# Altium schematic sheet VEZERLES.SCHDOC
size A2
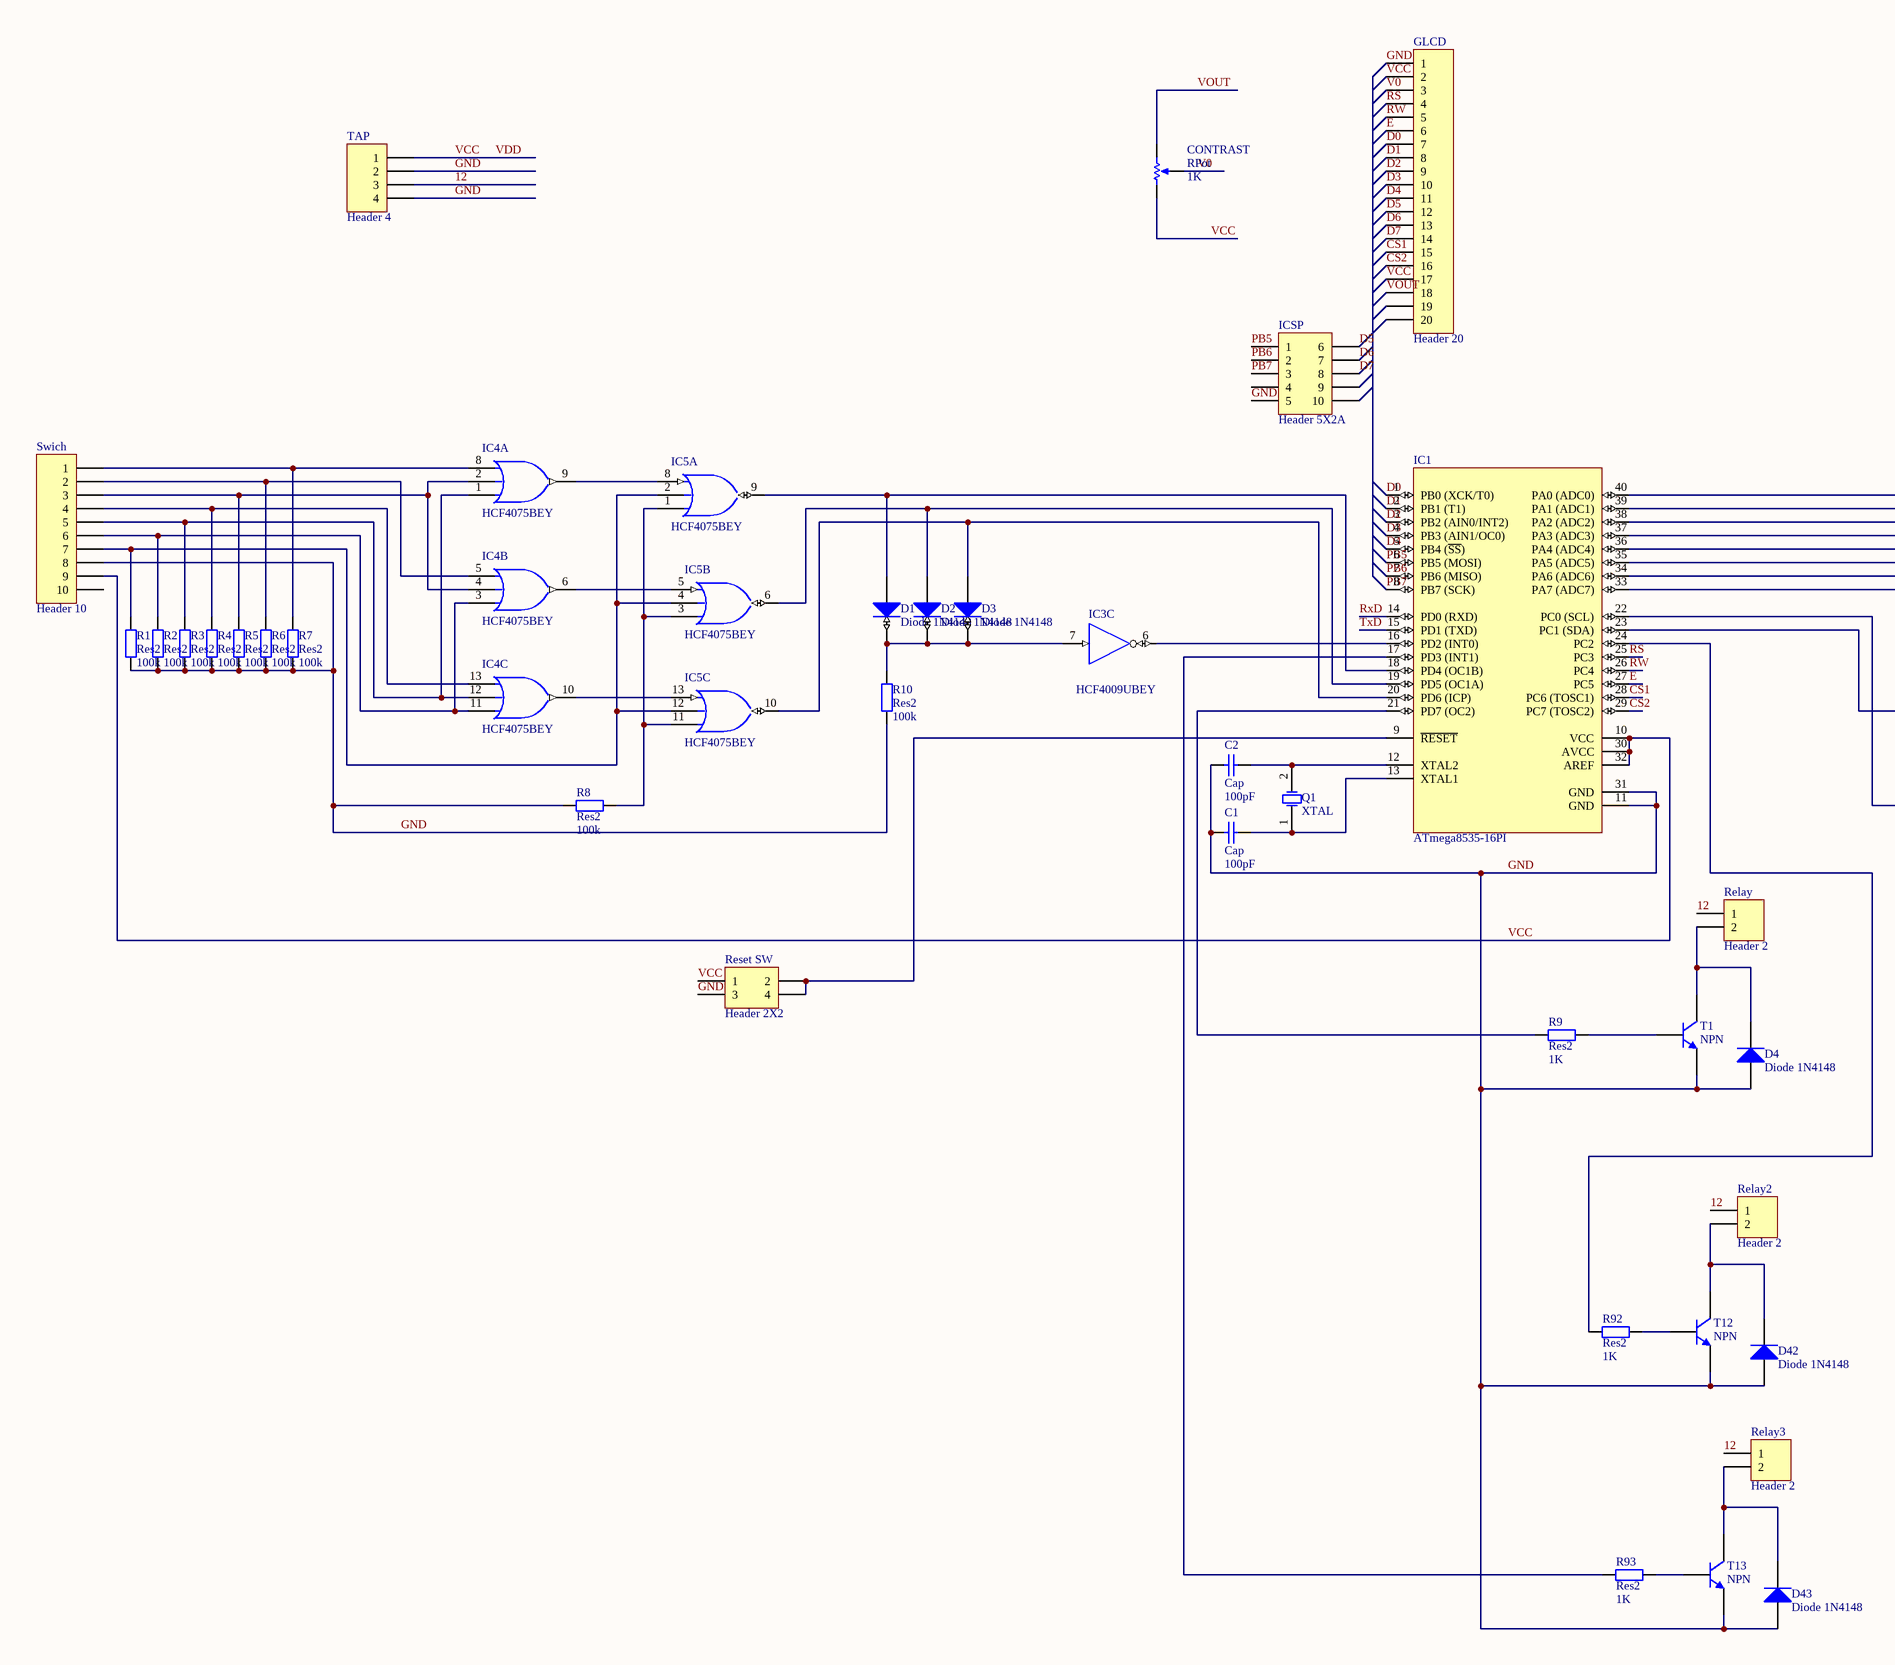
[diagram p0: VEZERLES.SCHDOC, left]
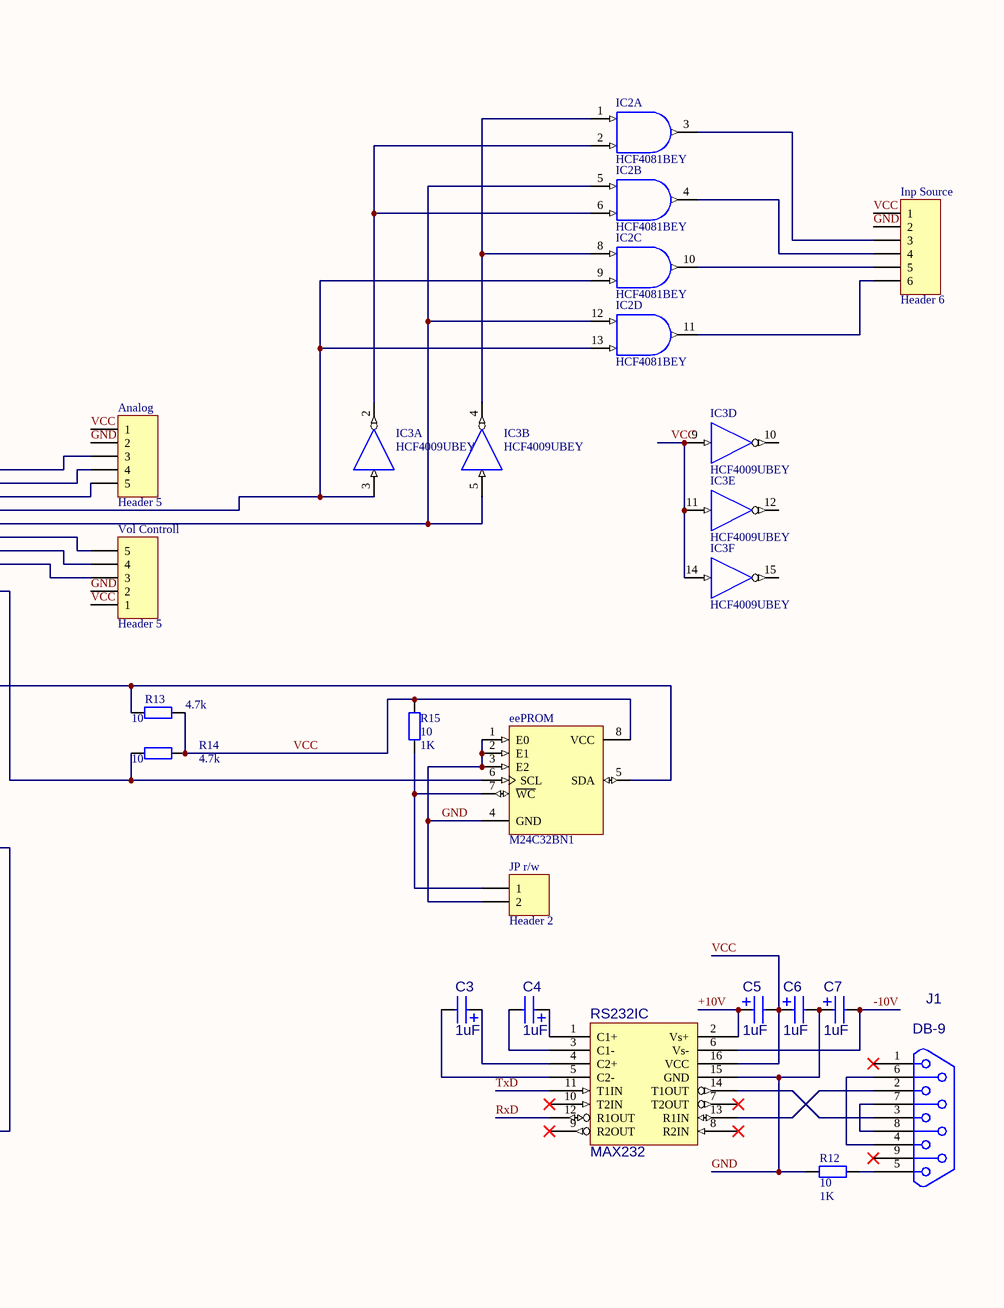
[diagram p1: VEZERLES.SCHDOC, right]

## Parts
Analog  Header 5  [HDR1X5]
C1  Cap  value 100pF  [CAPR2.54-5.1X3.2]
C2  Cap  value 100pF  [CAPR2.54-5.1X3.2]
C3  1uF  [CAPPR1.5-4X5]
C4  1uF  [CAPPR1.5-4X5]
C5  1uF  [CAPPR1.5-4X5]
C6  1uF  [CAPPR1.5-4X5]
C7  1uF  [CAPPR1.5-4X5]
CONTRAST  RPot  value 1K  [VR5]
D1  Diode 1N4148  [DIO7.1-3.9x1.9]
D2  Diode 1N4148  [DIO7.1-3.9x1.9]
D3  Diode 1N4148  [DIO7.1-3.9x1.9]
D4  Diode 1N4148  [DIO7.1-3.9x1.9]
D42  Diode 1N4148  [DIO7.1-3.9x1.9]
D43  Diode 1N4148  [DIO7.1-3.9x1.9]
eePROM  M24C32BN1  [PSDIP8A]
GLCD  Header 20  [HDR1X20]
IC1  ATmega8535-16PI  [40P6]
IC2  HCF4081BEY  [DIP14]  (parts A,B,C,D of 4)
IC3  HCF4009UBEY  [DIP16]  (parts A,B,C,D,E,F of 6)
IC4  HCF4075BEY  [DIP14]  (parts A,B,C of 3)
IC5  HCF4075BEY  [DIP14]  (parts A,B,C of 3)
ICSP  Header 5X2A  [HDR2X5_CEN]
Inp_Source  Header 6  [HDR1X6]
J1  DB-9  [DSUB1.385-2H9]
JP_r/w  Header 2  [HDR1X2]
Q1  XTAL  [BCY-W2/D3.1]
R1  Res2  value 100k  [AXIAL-0.4]
R2  Res2  value 100k  [AXIAL-0.4]
R3  Res2  value 100k  [AXIAL-0.4]
R4  Res2  value 100k  [AXIAL-0.4]
R5  Res2  value 100k  [AXIAL-0.4]
R6  Res2  value 100k  [AXIAL-0.4]
R7  Res2  value 100k  [AXIAL-0.4]
R8  Res2  value 100k  [AXIAL-0.4]
R9  Res2  value 1K  [AXIAL-0.4]
R10  Res2  value 100k  [AXIAL-0.4]
R12  10  value 1K  [AXIAL-0.4]
R13  10  value 4.7k  [AXIAL-0.4]
R14  10  value 4.7k  [AXIAL-0.4]
R15  10  value 1K  [AXIAL-0.4]
R92  Res2  value 1K  [AXIAL-0.4]
R93  Res2  value 1K  [AXIAL-0.4]
Relay  Header 2  [HDR1X2]
Relay2  Header 2  [HDR1X2]
Relay3  Header 2  [HDR1X2]
Reset_SW  Header 2X2  [HDR2X2]
RS232IC  MAX232  [DIP16]
Swich  Header 10  [HDR1X10]
T1  NPN  [BCY-W3]
T12  NPN  [BCY-W3]
T13  NPN  [BCY-W3]
TAP  Header 4  [HDR1X4]
Vol_Controll  Header 5  [HDR1X5]

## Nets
GND: Analog.2 C1.1 C2.1 C6.2(NEGATIV) C7.1(POSITIV) D4.1(A) D42.1(A) D43.1(A) eePROM.1(E0) eePROM.2(E1) eePROM.3(E2) eePROM.4(GND) GLCD.1 IC1.11(GND) IC1.31(GND) IC2.7(GND) IC3.8(GND) IC4.7(GND) IC5.7(GND) ICSP.5 Inp_Source.2 JP_r/w.2 R1.1 R2.1 R3.1 R4.1 R5.1 R6.1 R7.1 R8.1 R10.1 R12.1 Reset_SW.3 RS232IC.15(GND) Swich.8 T1.3(E) T12.3(E) T13.3(E) TAP.2 TAP.4 Vol_Controll.2
VCC: Analog.1 C5.2(NEGATIV) C6.1(POSITIV) CONTRAST.1(TOP) eePROM.8(VCC) GLCD.2 GLCD.17 IC1.10(VCC) IC1.30(AVCC) IC1.32(AREF) IC2.14(VDD) IC3.1(VCC) IC3.9(D) IC3.11(E) IC3.14(F) IC3.16(VCC) IC4.14(VDD) IC5.14(VDD) Inp_Source.1 R13.2 R14.2 R15.2 Reset_SW.1 RS232IC.16(VCC) Swich.9 TAP.1 Vol_Controll.1  [also labelled VDD]
12: Relay.1 Relay2.1 Relay3.1 TAP.3
+10V: C5.1(POSITIV) RS232IC.2(Vs+)
-10V: C7.2(NEGATIV) RS232IC.6(Vs-)
CS1: GLCD.15 IC1.28(PC6_(TOSC1))
CS2: GLCD.16 IC1.29(PC7_(TOSC2))
D0: GLCD.7 IC1.1(PB0_(XCK/T0))
D1: GLCD.8 IC1.2(PB1_(T1))
D2: GLCD.9 IC1.3(PB2_(AIN0/INT2))
D3: GLCD.10 IC1.4(PB3_(AIN1/OC0))
D4: GLCD.11 IC1.5(PB4_(~{SS}))
D5: GLCD.12 ICSP.6
D6: GLCD.13 ICSP.7
D7: GLCD.14 ICSP.8
E: GLCD.6 IC1.27(PC5)
PB5: IC1.6(PB5_(MOSI)) ICSP.1
PB6: IC1.7(PB6_(MISO)) ICSP.2
PB7: IC1.8(PB7_(SCK)) ICSP.3
RS: GLCD.4 IC1.25(PC3)
RW: GLCD.5 IC1.26(PC4)
RxD: IC1.14(PD0_(RXD)) RS232IC.12(R1OUT)
TxD: IC1.15(PD1_(TXD)) RS232IC.11(T1IN)
V0: CONTRAST.3(TAP) GLCD.3
VOUT: CONTRAST.2(BOT) GLCD.18
NetAnalog_3: Analog.3 IC1.40(PA0_(ADC0))
NetAnalog_4: Analog.4 IC1.39(PA1_(ADC1))
NetAnalog_5: Analog.5 IC1.38(PA2_(ADC2))
NetC1_2: C1.2 IC1.13(XTAL1) Q1.1(OSC1)
NetC2_2: C2.2 IC1.12(XTAL2) Q1.2(OSC2)
NetC3_1: C3.1(POSITIV) RS232IC.4(C2+)
NetC3_2: C3.2(NEGATIV) RS232IC.5(C2-)
NetC4_1: C4.1(POSITIV) RS232IC.1(C1+)
NetC4_2: C4.2(NEGATIV) RS232IC.3(C1-)
NetD1_1: D1.1(A) IC1.18(PD4_(OC1B)) IC5.9(J)
NetD1_2: D1.2(K) D2.2(K) D3.2(K) IC3.7(C) R10.2
NetD2_1: D2.1(A) IC1.19(PD5_(OC1A)) IC5.6(K)
NetD3_1: D3.1(A) IC1.20(PD6_(ICP)) IC5.10(L)
NetD4_2: D4.2(K) Relay.2 T1.1(C)
NetD42_2: D42.2(K) Relay2.2 T12.1(C)
NetD43_2: D43.2(K) Relay3.2 T13.1(C)
NeteePROM_5: eePROM.5(SDA) IC1.23(PC1_(SDA)) R13.1
NeteePROM_6: eePROM.6(SCL) IC1.22(PC0_(SCL)) R14.1
NeteePROM_7: eePROM.7(~{WC}) JP_r/w.1 R15.1
NetIC1_9: IC1.9(~{RESET}) Reset_SW.2 Reset_SW.4
NetIC1_16: IC1.16(PD2_(INT0)) IC3.6(I)
NetIC1_17: IC1.17(PD3_(INT1)) R93.1
NetIC1_21: IC1.21(PD7_(OC2)) R9.1
NetIC1_24: IC1.24(PC2) R92.1
NetIC1_33: IC1.33(PA7_(ADC7)) Vol_Controll.3
NetIC1_34: IC1.34(PA6_(ADC6)) Vol_Controll.4
NetIC1_35: IC1.35(PA5_(ADC5)) Vol_Controll.5
NetIC1_36: IC1.36(PA4_(ADC4)) IC2.5(C) IC2.12(G) IC3.5(B)
NetIC1_37: IC1.37(PA3_(ADC3)) IC2.9(F) IC2.13(H) IC3.3(A)
NetIC2_1: IC2.1(A) IC2.8(E) IC3.4(H)
NetIC2_2: IC2.2(B) IC2.6(D) IC3.2(G)
NetIC2_3: IC2.3(J) Inp_Source.3
NetIC2_4: IC2.4(K) Inp_Source.4
NetIC2_10: IC2.10(L) Inp_Source.5
NetIC2_11: IC2.11(M) Inp_Source.6
NetIC4_1: IC4.1(C) IC4.12(H) R3.2 Swich.5
NetIC4_2: IC4.2(B) IC4.4(E) R5.2 Swich.3
NetIC4_3: IC4.3(F) IC4.11(I) R2.2 Swich.6
NetIC4_5: IC4.5(D) R6.2 Swich.2
NetIC4_6: IC4.6(K) IC5.5(D)
NetIC4_8: IC4.8(A) R7.2 Swich.1
NetIC4_9: IC4.9(J) IC5.8(A)
NetIC4_10: IC4.10(L) IC5.13(G)
NetIC4_13: IC4.13(G) R4.2 Swich.4
NetIC5_1: IC5.1(C) IC5.3(F) IC5.11(I) R8.2
NetIC5_2: IC5.2(B) IC5.4(E) IC5.12(H) R1.2 Swich.7
NetJ1_2: J1.2 RS232IC.13(R1IN)
NetJ1_3: J1.3 RS232IC.14(T1OUT)
NetJ1_4: J1.4 J1.6
NetJ1_5: J1.5 R12.2
NetJ1_7: J1.7 J1.8
NetR9_2: R9.2 T1.2(B)
NetR92_2: R92.2 T12.2(B)
NetR93_2: R93.2 T13.2(B)

Not connected (* = marked no-connect by the designer): GLCD 19 20; IC3 10(J) 12(K) 15(L); ICSP 4 9 10; J1 1* 9*; RS232IC 7(T2OUT)* 8(R2IN)* 9(R2OUT)* 10(T2IN)*; Swich 10

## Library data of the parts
Analog Vol_Controll = Header 5: Header, 5-Pin
C1 C2 = Cap: Capacitor
C3-C7 = CPOL: Elektrolit kondenzátor
CONTRAST = RPot: Potentiometer; Set Position: 0.5
D1-D4 D42 D43 = Diode 1N4148: High Conductance Fast Diode; Revision 1: 11-Jul-2000: SIM Model Added.; Revision 2: 17-Jul-2002: Re-released for DXP Platform.; Code - JEDEC: DO-204-AH
eePROM = M24C32BN1: 32 Kbit Serial I²C Bus EEPROM; Package Information: Latest Revision: Jun-1998
GLCD = Header 20: Header, 20-Pin
IC1 = ATmega8535-16PI: 8-Bit AVR Microcontroller with 8K Bytes of In-System Programmable Flash Memory; Package Information: Latest Revision: Dec-1999
IC2 = HCF4081BEY: Quad 2-Input AND Gate; Revision 1: 29-Sep-2000: Name of VCC pin changed to VDD.; Revision 2: 17-Jul-2002: Re-released for DXP Platform.; Package Information: Latest Revision: Jan-1997
IC3 = HCF4009UBEY: Hex Buffer/Converter; Package Information: Latest Revision: Nov-1996; Note: Pin 13 is not connected and not drawn.
IC4 IC5 = HCF4075BEY: Triple 3-Input OR Gate; Revision 1: 29-Sep-2000: Name of VCC pin changed to VDD.; Revision 2: 17-Jul-2002: Re-released for DXP Platform.; Package Information: Latest Revision: Jan-1997
ICSP = Header 5X2A: Header, 5-Pin, Dual row
Inp_Source = Header 6: Header, 6-Pin
J1 = DB9
JP_r/w Relay Relay2 Relay3 = Header 2: Header, 2-Pin
Q1 = XTAL: Crystal Oscillator
R1-R10 R12-R15 R92 R93 = Res2: Resistor
Reset_SW = Header 2X2: Header, 2-Pin, Dual row
RS232IC = MAX232: DUAL EIA-232 DRIVER/RECEIVER
Swich = Header 10: Header, 10-Pin
T1 T12 T13 = NPN: NPN Bipolar Transistor; Code - JEDEC: TO-226-AA
TAP = Header 4: Header, 4-Pin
